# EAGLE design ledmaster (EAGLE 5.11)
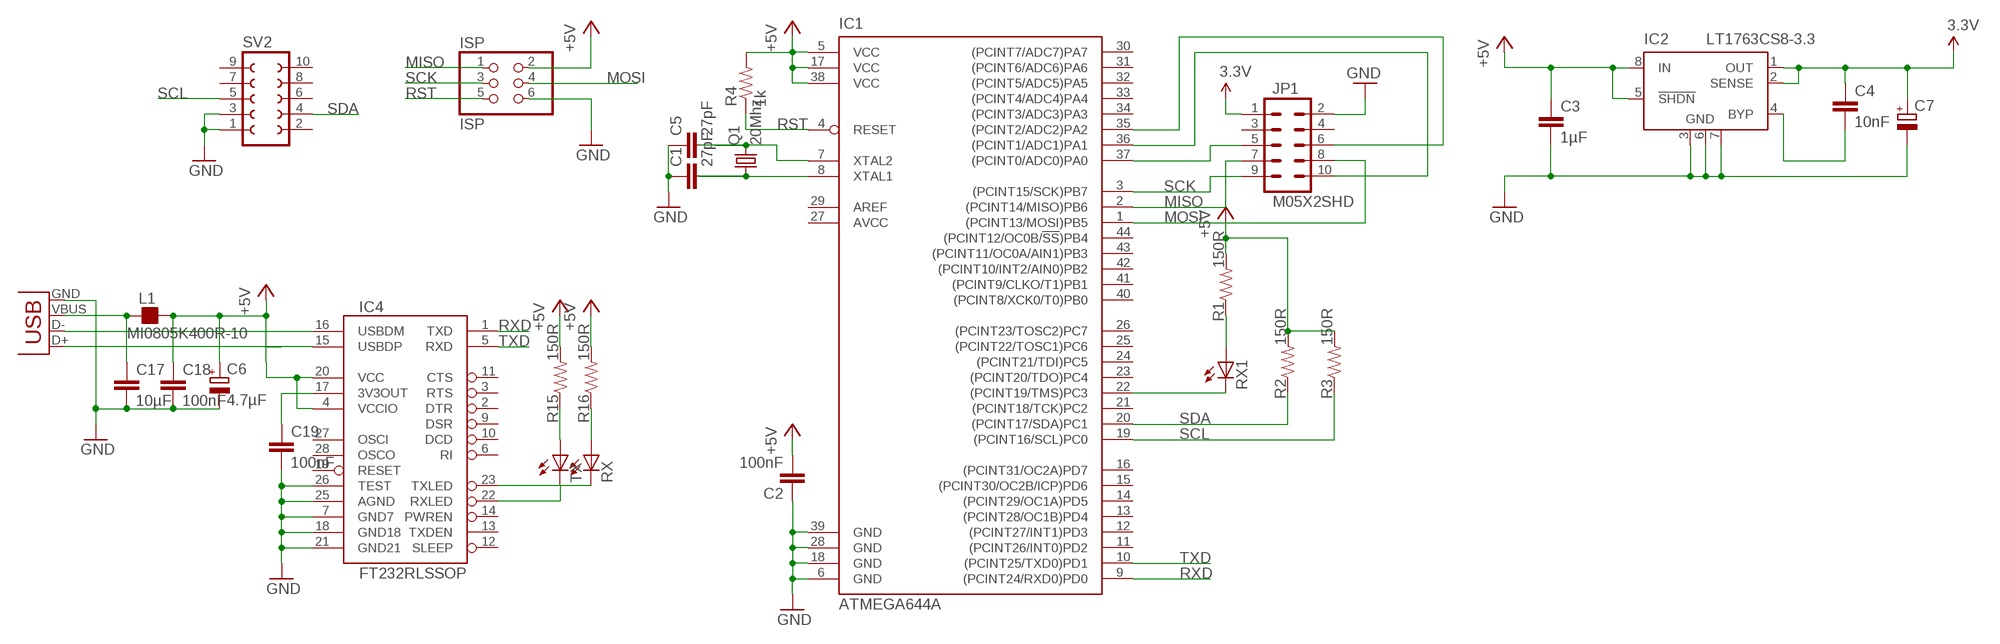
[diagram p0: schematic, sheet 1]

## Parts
C1  27pF  CAP0805  [0805]
C2  100nF  CAP0805  [0805]
C3  1µF  CAP0805  [0805]
C4  10nF  CAP0805  [0805]
C5  27pF  CAP0805  [0805]
C6  4.7µF  CPOL-EUSMCC  [SMC_C]
C7  CPOL-EUSMCC  [SMC_C]
C17  10µF  CAP0805  [0805]
C18  100nF  CAP0805  [0805]
C19  100nF  CAP0805  [0805]
IC1  ATMEGA644A  [TQFP44]
IC2  LT1763CS8-3.3  [SOIC8]
IC4  FT232RLSSOP  [SSOP28DB]
ISP  ISP  PINHD-2X03_2.54  [2X03]
JP1  M05X2SHD  [2X5-SHROUDED]
L1  MI0805K400R-10  FB_0805  [L0805]
Q1  20Mhz  CRYSTALCTS406  [CTS406]
R1  150R  RESISTOR  [0805]
R2  150R  RESISTOR  [0805]
R3  150R  RESISTOR  [0805]
R4  1k  RESISTOR  [0805]
R15  150R  RESISTOR  [0805]
R16  150R  RESISTOR  [0805]
RX  LEDCHIP-LED0805  [CHIP-LED0805]
RX1  LEDCHIP-LED0805  [CHIP-LED0805]
SV2  FE05-2W  [FE05-2W]
TX  LEDCHIP-LED0805  [CHIP-LED0805]
X1  USB-SMD-NS  [USB-MINIB-NOSTOP]

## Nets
3.3V: C4.1 C7.+ IC2.1(OUT) IC2.2(SENSE) JP1.1
+5V: C2.2 C3.1 C6.+ C18.1 IC1.5(VCC) IC1.17(VCC) IC1.38(VCC) IC2.5(!SHDN) IC2.8(IN) IC4.4(VCCIO) IC4.20(VCC) ISP.2 L1.2 R1.2 R2.2 R3.2 R4.2 R15.2 R16.2
GND: C1.1 C2.1 C3.2 C5.1 C6.- C7.- C17.2 C18.2 C19.2 IC1.6(GND) IC1.18(GND) IC1.28(GND) IC1.39(GND) IC2.3(GND) IC2.6(GND) IC2.7(GND) IC4.7(GND7) IC4.18(GND18) IC4.21(GND21) IC4.25(AGND) IC4.26(TEST) ISP.6 JP1.2 SV2.1 SV2.3 X1.GND
MISO: IC1.2((PCINT14/MISO)PB6) ISP.1 JP1.7
MOSI: IC1.1((PCINT13/MOSI)PB5) ISP.4 JP1.8
N$1: IC4.16(USBDM) X1.D-
N$2: IC4.15(USBDP) X1.D+
N$3: C4.2 IC2.4(BYP)
N$4: C17.1 L1.1 X1.VBUS
N$5: R1.1 RX1.A
N$6: IC1.22((PCINT19/TMS)PC3) RX1.C
N$7: IC1.37((PCINT0/ADC0)PA0) JP1.5
N$8: IC1.36((PCINT1/ADC1)PA1) JP1.10
N$9: IC1.35((PCINT2/ADC2)PA2) JP1.6
N$19: R15.1 TX.A
N$20: R16.1 RX.A
N$27: IC4.22(RXLED) TX.C
N$28: IC4.23(TXLED) RX.C
N$29: C19.1 IC4.17(3V3OUT)
N$30: C5.2 IC1.7(XTAL2) Q1.3
N$32: C1.2 IC1.8(XTAL1) Q1.1
RST: IC1.4(RESET) ISP.5 R4.1
RXD: IC1.9((PCINT24/RXD0)PD0) IC4.1(TXD)
SCK: IC1.3((PCINT15/SCK)PB7) ISP.3 JP1.9
SCL: IC1.19((PCINT16/SCL)PC0) R3.1 SV2.5
SDA: IC1.20((PCINT17/SDA)PC1) R2.1 SV2.4
TXD: IC1.10((PCINT25/TXD0)PD1) IC4.5(RXD)
Unconnected: IC1.11((PCINT26/INT0)PD2) IC1.12((PCINT27/INT1)PD3) IC1.13((PCINT28/OC1B)PD4) IC1.14((PCINT29/OC1A)PD5) IC1.15((PCINT30/OC2B/ICP)PD6) IC1.16((PCINT31/OC2A)PD7) IC1.21((PCINT18/TCK)PC2) IC1.23((PCINT20/TDO)PC4) IC1.24((PCINT21/TDI)PC5) IC1.25((PCINT22/TOSC1)PC6) IC1.26((PCINT23/TOSC2)PC7) IC1.29(AREF) IC1.30((PCINT7/ADC7)PA7) IC1.31((PCINT6/ADC6)PA6) IC1.32((PCINT5/ADC5)PA5) IC1.33((PCINT4/ADC4)PA4) IC1.34((PCINT3/ADC3)PA3) IC1.40((PCINT8/XCK0/T0)PB0) IC1.41((PCINT9/CLKO/T1)PB1) IC1.42((PCINT10/INT2/AIN0)PB2) IC1.43((PCINT11/OC0A/AIN1)PB3) IC1.44((PCINT12/OC0B/!SS!)PB4) IC4.2(DTR) IC4.3(RTS) IC4.6(RI) IC4.9(DSR) IC4.10(DCD) IC4.11(CTS) IC4.12(SLEEP) IC4.13(TXDEN) IC4.14(PWREN) IC4.19(RESET) IC4.27(OSCI) IC4.28(OSCO) JP1.3 JP1.4 SV2.2 SV2.6 SV2.7 SV2.8 SV2.9 SV2.10

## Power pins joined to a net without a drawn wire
AVCC: IC1.27(AVCC)

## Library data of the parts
C1-C5 C17-C19 = SparkFun:CAP: Capacitor
C6 C7 = resistor:CPOL-EU: POLARIZED CAPACITOR, European symbol
IC1 = atmel:ATMEGA644: 8-bit Microcontroller with 64K Bytes In-System Programmable Flash Source: http://www.atmel.com/dyn/resources/prod_documents/doc2593.pdf; MPN: ATMEGA644PV-10AU; OC_FARNELL: 1455123; OC_NEWARK: 58M3748
IC2 = linear-technology:LT1763CS8: 500mA, Low Noise, LDO Micropower Regulators Source: http://cds.linear.com/docs/Datasheet/1763ff.pdf
IC4 = SparkFun:FT232RL: USB UART FT232RL 4th Generation USB UART (USB <-> Serial) Controller. Spark Fun Electronics SKU : COM-00650
ISP = pinhead-2:PINHD-2X03: PIN HEADER
JP1 = SparkFun:M05X2: Header 5x2 Standard 10-pin dual row 0.1" header. Commonly used with AVR-ISP. Use with Spark Fun Electronics SKU: PRT-00778
L1 = rc-master-smd:FB_: FERRITE BEAD
Q1 = crystal:CRYSTAL: CRYSTAL
R1-R4 R15 R16 = SparkFun:RESISTOR: Resistor
RX RX1 TX = led:LED: LED
SV2 = con-lsta:FE05-2W: FEMALE HEADER
X1 = SparkFun:USB: USB Connectors USB-B-PTH is fully proven SKU : PRT-00139 USB-miniB is fully proven SKU : PRT-00587 USB-A-PCB is untested. USB-A-H is throughly reviewed, but untested. Spark Fun Electronics SKU : PRT-00437 USB-B-SMT is throughly reviewed, but untested. Needs silkscreen touching up. USB-A-S has not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

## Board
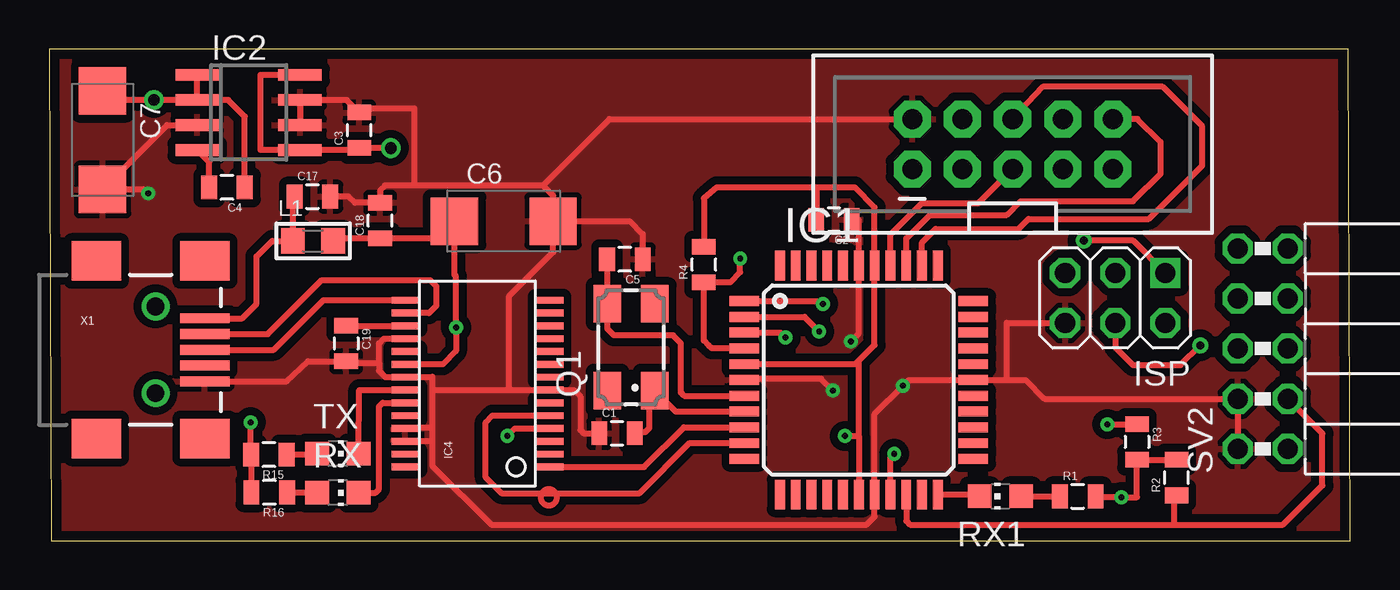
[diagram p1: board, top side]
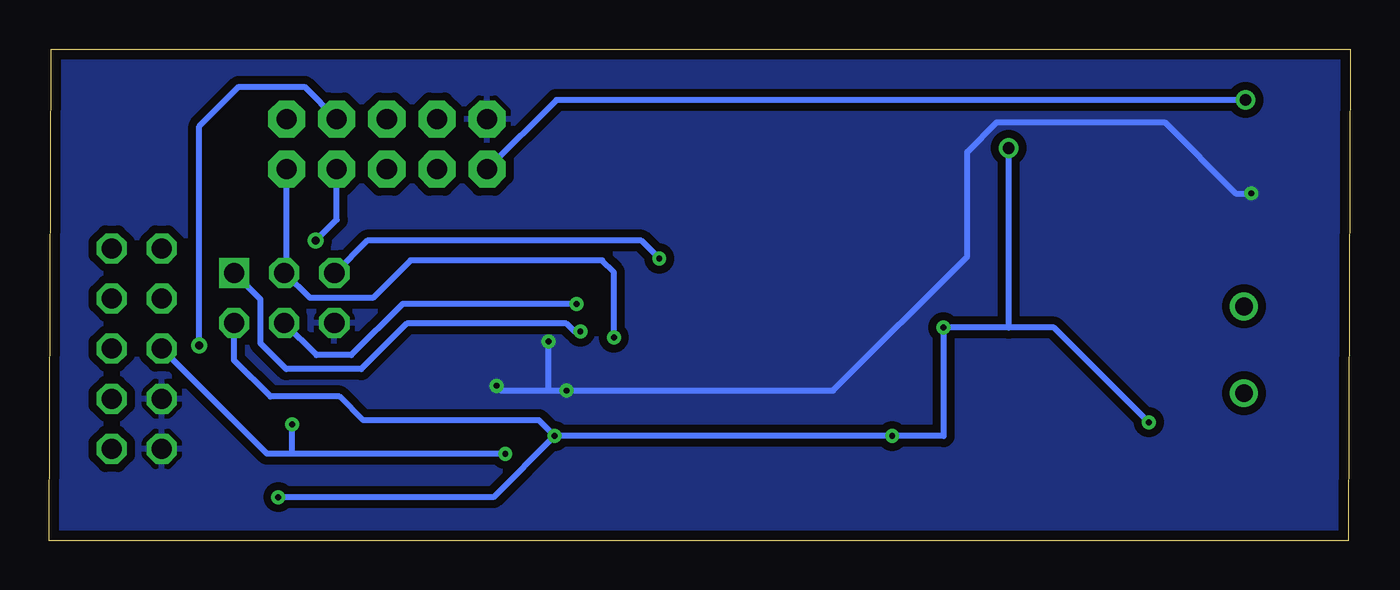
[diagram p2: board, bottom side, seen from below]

Size 65.9 x 24.9 mm. Coordinates in mm from the lower left corner, seen from the top.
Outline: 0.1,0 65.9,0 65.8,24.9 0,24.9 0.1,0
Copper layers (1*16): Top 0.035mm / dielectric 1.5mm / Bottom 0.035mm
Design rules "default *": minimum track width 10mil, minimum drill 0.3mm, track to track 8mil, track to pad 8mil, pad to pad 8mil, via to via 8mil, smd to smd 8mil, copper to edge 20mil, drill to drill 8mil, minimum pad ring 10mil, minimum via ring 8mil, stop-mask expansion 4mil, vias tented up to drill 30mil, thermal gap 10mil

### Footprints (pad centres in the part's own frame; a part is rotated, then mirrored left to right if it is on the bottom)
0805 = smd 0.8 x 1.2: 1 -0.9,0; 2 0.9,0
SMC_C = smd 2.4 x 2.4: + -2.5,0; - 2.5,0
TQFP44 = smd 1.5 x 0.5: 1 -5.8,4; 2 -5.8,3.2; 3 -5.8,2.4; 4 -5.8,1.6; 5 -5.8,0.8; 6 -5.8,0; 7 -5.8,-0.8; 8 -5.8,-1.6; 9 -5.8,-2.4; 10 -5.8,-3.2; 11 -5.8,-4; 23 5.8,-4; 24 5.8,-3.2; 25 5.8,-2.4; 26 5.8,-1.6; 27 5.8,-0.8; 28 5.8,0; 29 5.8,0.8; 30 5.8,1.6; 31 5.8,2.4; 32 5.8,3.2; 33 5.8,4 | smd 0.5 x 1.5: 12 -4,-5.8; 13 -3.2,-5.8; 14 -2.4,-5.8; 15 -1.6,-5.8; 16 -0.8,-5.8; 17 0,-5.8; 18 0.8,-5.8; 19 1.6,-5.8; 20 2.4,-5.8; 21 3.2,-5.8; 22 4,-5.8; 34 4,5.8; 35 3.2,5.8; 36 2.4,5.8; 37 1.6,5.8; 38 0.8,5.8; 39 0,5.8; 40 -0.8,5.8; 41 -1.6,5.8; 42 -2.4,5.8; 43 -3.2,5.8; 44 -4,5.8
SOIC8 = smd 0.6 x 2.2: 1 -1.905,-2.6; 2 -0.635,-2.6; 3 0.635,-2.6; 4 1.905,-2.6; 5 1.905,2.6; 6 0.635,2.6; 7 -0.635,2.6; 8 -1.905,2.6
SSOP28DB = smd 0.348 x 1.397: 1 -4.225,-3.656; 2 -3.575,-3.656; 3 -2.925,-3.656; 4 -2.275,-3.656; 5 -1.625,-3.656; 6 -0.975,-3.656; 7 -0.325,-3.656; 8 0.325,-3.656; 9 0.975,-3.656; 10 1.625,-3.656; 11 2.275,-3.656; 12 2.925,-3.656; 13 3.575,-3.656; 14 4.225,-3.656; 15 4.225,3.656; 16 3.575,3.656; 17 2.925,3.656; 18 2.275,3.656; 19 1.625,3.656; 20 0.975,3.656; 21 0.325,3.656; 22 -0.325,3.656; 23 -0.975,3.656; 24 -1.625,3.656; 25 -2.275,3.656; 26 -2.925,3.656; 27 -3.575,3.656; 28 -4.225,3.656
2X03 = drill 1.016 square: 1 -2.54,-1.27 | drill 1.016 octagon: 2 -2.54,1.27; 3 0,-1.27; 4 0,1.27; 5 2.54,-1.27; 6 2.54,1.27
2X5-SHROUDED = drill 1.016 pad 1.88 octagon: 1 -1.27,5.08; 2 1.27,5.08; 3 -1.27,2.54; 4 1.27,2.54; 5 -1.27,0; 6 1.27,0; 7 -1.27,-2.54; 8 1.27,-2.54; 9 -1.27,-5.08; 10 1.27,-5.08
L0805 = smd 1.2 x 1.3: 1 -1.016,0; 2 1.016,0
CTS406 = smd 1.9 x 1.4: 1 -2.2,-1.2; 2 2.2,-1.2; 3 2.2,1.2; 4 -2.2,1.2
CHIP-LED0805 = smd 1.2 x 1.2: A 0,-1.05; C 0,1.05
FE05-2W = drill 1.016 octagon: 1 -5.08,1.27; 2 -5.08,-1.27; 3 -2.54,1.27; 4 -2.54,-1.27; 5 0,1.27; 6 0,-1.27; 7 2.54,1.27; 8 2.54,-1.27; 9 5.08,1.27; 10 5.08,-1.27
USB-MINIB-NOSTOP = smd 2.5 x 0.5: D+ 2.5,0; D- 2.5,0.8; GND 2.5,-1.6; ID 2.5,-0.8; VBUS 2.5,1.6 | smd 2.5 x 2: G1 -3,-4.5; G2 -3,4.5; G3 2.5,4.5; G4 2.5,-4.5 | drill 0.9 pad 0.8 round: H1 0,2.2 | drill 0.9 pad 0.787 round: H2 0,-2.2

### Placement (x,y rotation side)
C1  28.76,5.44 0 top
C2  39.75,16.26 180 top
C3  15.7,20.8 90 top
C4  9,17.9 180 top
C5  29.16,14.26 180 top
C6  23.02,16.19 0 top
C7  2.7,20.3 270 top
C17  13.33,17.44 0 top
C18  16.76,16.22 90 top
C19  15.04,9.99 270 top
IC1  41.01,8.14 0 top
IC2  10.1,21.7 270 top
IC4  21.69,7.96 90 top
ISP  54,12.3 180 top
JP1  48.8,20.1 90 top
L1  13.36,15.19 0 top
Q1  29.47,9.8 90 top
R1  52.1,2.24 0 top
R2  57.1,3.2 90 top
R3  55.1,5 270 top
R4  33.16,13.99 90 top
R15  11.12,4.36 180 top
R16  11.14,2.45 180 top
RX  14.62,2.43 270 top
RX1  48.18,2.25 90 top
SV2  61.47,9.73 90 top
TX  14.62,4.41 270 top
X1  5.38,9.67 0 top

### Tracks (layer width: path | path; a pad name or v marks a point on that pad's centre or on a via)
3.3V  (via drill 0.6)
  Top 0.305: C7.+ 3.17,22.34 v5.3,22.34 IC2.2 | IC2.2 IC2.1 | C4.1 9.9,21.5 9.06,22.34 IC2.2
  Bottom 0.305: v5.3,22.34 20.2,22.34 20.9,22.34 40.22,22.34 JP1.1
+5V  (via drill 0.3, 0.6)
  Top 0.305: L1.2 14.51,15.32 C18.1 19.75,15.32 C6.+ 20.52,13.48 20.6,13.4 v20.6,10.8 20.6,9.6 19.94,8.93 IC4.20 | 10.24,4.34 R15.2 | R16.2 10.24,4.34 | 10.24,4.34 10.2,4.34 v10.2,6 | IC1.5 40.84,8.94 40.95,9.05 | 40.95,9.05 41.81,9.91 IC1.38 41.81,16.89 40.8,17.9 38.85,17.9 | 41.01,5.3 41.01,8.99 40.95,9.05 | v23.2,5.3 23.59,5.68 IC4.4 | v40.3,5.3 41.01,5.3 | 41.01,5.3 IC1.17 | v54.3,2.2 54.26,2.24 | R2.2 R3.2 55.1,2.2 v54.3,2.2 | R1.2 53,2.2 v54.3,2.2 | R4.2 33.16,17.36 33.8,17.9 38.85,17.9 | IC2.8 10.7,23.6 10.7,19.8 IC2.5 15.7,19.8 C3.1 v17.3,19.9 | 38.85,17.9 C2.2
  Bottom 0.305: v10.2,6 15,10.8 17.3,10.8 | v40.3,5.3 v23.2,5.3 20.6,5.3 v20.6,10.8 17.3,10.8 | v54.3,2.2 43.4,2.2 v40.3,5.3 | ISP.2 56.54,9.14 54.7,7.3 51.2,7.3 50,6.1 41.1,6.1 v40.3,5.3 | 17.3,10.8 v17.3,19.9
GND  (via drill 0.3)
  Top 0.305: 19.4,7.63 19.4,8.3 18.05,8.3 IC4.21 17.02,8.28 16.7,8.6 16.7,9 | IC4.25 18.05,5.7 19.4,5.7 | C17.2 15.16,17.44 15.48,17.12 C18.2 16.76,17.76 17,18 18.5,18 | 25,18 25.52,17.48 C6.- | IC4.18 16.94,10.23 16.7,10 16.7,9 | 19.4,7.63 23.4,7.63 | 23.4,7.63 IC4.7 26.57,7.63 26.9,7.3 26.9,5.6 27.06,5.44 C1.1 | 19.4,7.63 19.4,5.7 | X1.GND 12.03,8.07 13.11,9.09 C19.2 15.13,9 16.7,9 | C5.1 30.06,15.54 29.41,16.19 C6.- | C6.- 25.52,14.62 23.3,12.4 23.3,7.73 23.4,7.63 | IC1.6 35.27,8.2 39.1,8.2 v39.7,7.6 | v40.6,10.1 41.01,10.51 IC1.39 41.01,16.26 C2.1 | 19.4,5.03 19.4,3.8 22.4,0.8 41.4,0.8 41.81,1.21 IC1.18 41.81,6.41 v43.25,7.85 43.54,8.14 IC1.28 48.5,8.14 | 19.4,5.03 IC4.26 | 19.4,5.7 19.4,5.03 | SV2.1 SV2.3 50.41,7.19 49.46,8.14 48.5,8.14 | ISP.6 48.5,11.03 48.5,8.14 | IC2.6 IC2.7 15.06,22.34 C3.2 15.7,21.9 18.5,21.9 18.5,18 | C7.- 5.96,21.06 IC2.3 | 25,18 18.5,18 | C7.- 2.7,17.6 | v5,17.6 4.8,17.8 C7.- | JP1.2 28.37,21.37 25,18
  Bottom 0.305: 40.7,7.6 43,7.6 v43.25,7.85 | 40.7,7.6 v39.7,7.6 26.2,7.6 19.4,14.4 19.4,19.7 17.9,21.2 9.4,21.2 5.8,17.6 v5,17.6 | v40.6,10.1 40.6,7.7 40.7,7.6
  pour Top (isolate 0.4): 0.1,-0.1 65.9,-0.1 65.9,24.9 0.1,24.9
  pour Bottom (isolate 0.4): 0.1,24.9 65.9,24.9 65.9,0 0.1,0
MISO  (via drill 0.3, 0.4)
  Top 0.305: IC1.2 38.26,11.34 v39,10.6 | v52.4,15.2 54.91,15.2 ISP.1
  Bottom 0.305: v39,10.6 39.3,10.6 39.7,11 47.8,11 50.1,8.7 53.9,8.7 55.2,10 55.2,12.23 ISP.1 | JP1.7 51.34,16.26 v52.4,15.2
MOSI  (via drill 0.3, 0.4)
  Top 0.305: IC1.1 39.06,12.14 v39.2,12 | v58.3,9.9 57.3,8.9 54.9,8.9 54,9.8 ISP.4
  Bottom 0.305: v39.2,12 48,12 50.6,9.4 52.37,9.4 ISP.4 | JP1.8 52.97,23 56.3,23 58.3,21 v58.3,9.9
N$1
  Top 0.305: X1.D- 11.07,10.47 13.8,13.2 19.3,13.2 19.6,12.9 19.6,11.9 19.24,11.53 IC4.16
N$2
  Top 0.305: IC4.15 13.88,12.18 11.37,9.67 X1.D+
N$3
  Top 0.305: C4.2 8.1,19.2 IC2.4
N$4
  Top 0.305: X1.VBUS 9.77,11.27 10.5,12 10.5,14.4 11.29,15.19 L1.1 12.34,17.35 C17.1
N$5
  Top 0.305: RX1.A R1.1
N$6
  Top 0.305: RX1.C 47.04,2.34 IC1.22
N$7
  Top 0.305: IC1.37 42.61,15.51 44.2,17.1 47.07,17.1 JP1.5
N$8
  Top 0.305: IC1.36 43.41,15.31 44.6,16.5 48.5,16.5 49.2,17.2 54.9,17.2 56.3,18.6 56.3,20.2 55.13,21.37 JP1.10
N$9
  Top 0.305: IC1.35 44.21,15.11 44.9,15.8 49.1,15.8 49.6,16.3 55.7,16.3 58.4,19 58.4,21 56.4,23 50.33,23 JP1.6
N$19
  Top 0.305: TX.A 13.52,4.36 R15.1
N$20
  Top 0.305: RX.A 13.55,2.45 R16.1
N$27
  Top 0.305: IC4.22 15.7,7.63 TX.C
N$28
  Top 0.305: IC4.23 16.89,6.98 16.7,6.8 16.7,2.6 16.53,2.43 RX.C
N$29
  Top 0.305: IC4.17 C19.1
N$30
  Top 0.305: IC1.7 32.16,7.34 32,7.5 32,10 31.6,10.4 28.6,10.4 28.27,10.73 Q1.3 28.27,14.07 C5.2
N$32
  Top 0.305: IC1.8 31.73,6.54 Q1.1 30.17,7.13 30.4,6.9 30.4,5.7 30.2,5.5 29.72,5.5 C1.2
RST  (via drill 0.3)
  Top 0.305: IC1.4 33.56,9.74 33.4,9.9 33.16,10.14 R4.1 34.5,13.1 35,13.6 v35,14.3
  Bottom 0.305: ISP.5 51.43,13.57 49.8,15.2 35.9,15.2 v35,14.3
RXD
  Top 0.305: IC1.9 32.14,5.74 30.14,3.73 IC4.1
SCK  (via drill 0.3)
  Top 0.305: v37.3,10.3 37.04,10.54 IC1.3
  Bottom 0.305: v37.3,10.3 37.3,13.6 37.9,14.2 47.6,14.2 49.5,12.3 52.7,12.3 53.97,13.57 ISP.3 53.88,13.69 JP1.9
SCL  (via drill 0.3)
  Top 0.305: IC1.19 42.61,4.21 v42.8,4.4 | v53.6,5.9 R3.1
  Bottom 0.305: v42.8,4.4 45.5,4.4 53.5,4.4 | 53.5,4.4 54.87,4.4 SV2.5 | v53.6,5.9 53.6,4.4 53.5,4.4
SDA
  Top 0.305: IC1.20 43.41,0.99 43.6,0.8 57,0.8 | 57,0.8 62.5,0.8 64.5,2.8 64.5,5.43 SV2.4 | R2.1 57,2.3 57,0.8
TXD
  Top 0.305: IC4.5 22.44,6.34 22.1,6 22.1,3.2 22.9,2.4 29.9,2.4 32.44,4.94 IC1.10
(copper drawn outside any net)
  shapes: Top circle x1

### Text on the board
tStop: LED-Master v2 | seb@exse.net <<</>> | GND
bStop: GND | LED-Master seb@exse.net <<</>>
